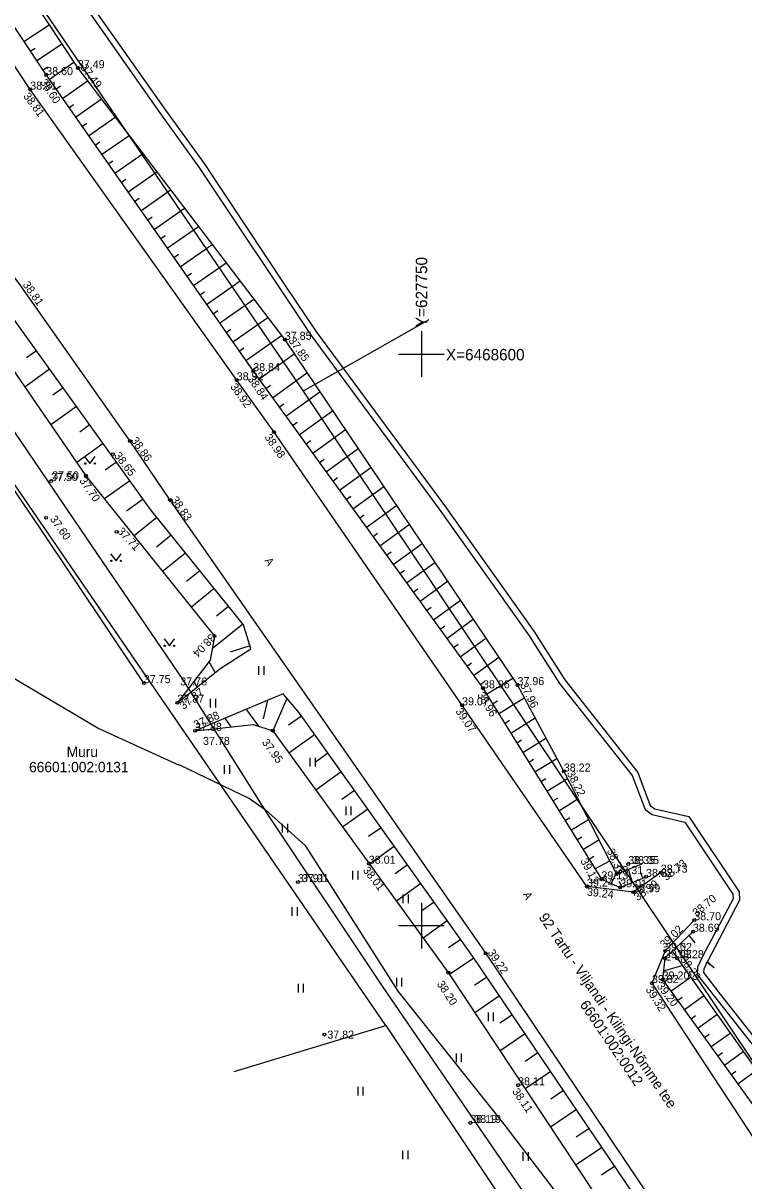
# Model space of a CAD drawing. Extents: x 627548 to 628052, y 6467984 to 6468802.
# Drawn here: x 627715.2 to 627778.2, y 6468527.7 to 6468629 of the extents above; entities that cross this region are included whole.
import ezdxf

# ---------------------------------------------------------------- set-up
doc = ezdxf.new("R2010")
doc.units = 0
for name, color, linetype in [('HALJASTUS', 7, 'Continuous'), ('KORGUS-EH2000', 7, 'Continuous'), ('KPKAABEL', 7, 'Continuous'), ('MOOTKORG-EH2000', 7, 'Continuous'), ('MOOTMPUNKT', 7, 'Continuous'), ('MPKAABEL', 7, 'Continuous'), ('PIIR', 7, 'Continuous'), ('RELJEEF', 7, 'Continuous'), ('SITRASS', 7, 'Continuous'), ('TEE', 7, 'Continuous'), ('VORK', 7, 'Continuous')]:
    doc.layers.add(name, color=color, linetype=linetype)

msp = doc.modelspace()

# ---------------------------------------------------------------- linework, layer by layer
at = {"layer": 'HALJASTUS'}
for p, q in [((627720.53, 6468591.03), (627720.99, 6468590.42)), ((627720.99, 6468590.42), (627721.44, 6468591.03)), ((627722.81, 6468582.51), (627723.28, 6468581.91)), ((627723.28, 6468581.91), (627723.72, 6468582.51)), ((627727.48, 6468575.09), (627727.95, 6468574.48)), ((627727.95, 6468574.48), (627728.39, 6468575.09)), ((627735.75, 6468572.71), (627735.75, 6468571.95)), ((627736.21, 6468572.71), (627736.21, 6468571.95)), ((627731.53, 6468569.84), (627731.53, 6468569.08)), ((627731.98, 6468569.84), (627731.98, 6468569.08)), ((627732.74, 6468564.03), (627732.74, 6468563.27)), ((627733.2, 6468564.03), (627733.2, 6468563.27)), ((627740.25, 6468564.67), (627740.25, 6468563.91)), ((627740.7, 6468564.67), (627740.7, 6468563.91)), ((627743.39, 6468560.42), (627743.39, 6468559.66)), ((627743.84, 6468560.42), (627743.84, 6468559.66)), ((627737.83, 6468558.9), (627737.83, 6468558.14)), ((627738.29, 6468558.9), (627738.29, 6468558.14)), ((627743.98, 6468554.8), (627743.98, 6468554.04)), ((627744.43, 6468554.8), (627744.43, 6468554.04)), ((627748.38, 6468552.72), (627748.38, 6468551.96)), ((627748.84, 6468552.72), (627748.84, 6468551.96)), ((627738.67, 6468551.61), (627738.67, 6468550.85)), ((627739.12, 6468551.61), (627739.12, 6468550.85)), ((627739.21, 6468544.9), (627739.21, 6468544.14)), ((627739.66, 6468544.9), (627739.66, 6468544.14)), ((627747.82, 6468545.44), (627747.82, 6468544.68)), ((627748.27, 6468545.44), (627748.27, 6468544.68)), ((627755.83, 6468542.39), (627755.83, 6468541.63)), ((627756.29, 6468542.39), (627756.29, 6468541.63)), ((627753.04, 6468538.8), (627753.04, 6468538.04)), ((627753.49, 6468538.8), (627753.49, 6468538.04)), ((627744.43, 6468535.89), (627744.43, 6468535.13)), ((627744.88, 6468535.89), (627744.88, 6468535.13)), ((627748.36, 6468530.31), (627748.36, 6468529.55)), ((627748.82, 6468530.31), (627748.82, 6468529.55)), ((627758.87, 6468530.18), (627758.87, 6468529.41)), ((627759.33, 6468530.18), (627759.33, 6468529.41))]:
    msp.add_line(p, q, dxfattribs=at)
msp.add_lwpolyline([(627725.71, 6468571.21), (627716.57, 6468584.87), (627692.41, 6468620.36), (627689.62, 6468619.76), (627687.7, 6468623.54), (627673.32, 6468620.74)], dxfattribs=at)
for centre in [(627720.59, 6468590.42), (627721.42, 6468590.42), (627722.87, 6468581.91), (627723.7, 6468581.91), (627727.54, 6468574.48), (627728.37, 6468574.48)]:
    msp.add_circle(centre, 0.055, dxfattribs=at)
at = {"layer": 'KORGUS-EH2000'}
for centre in [(627737.11, 6468593.18), (627724.5, 6468592.39), (627723.01, 6468591.24), (627720.65, 6468589.36), (627727.99, 6468587.24), (627717.17, 6468585.68), (627723.32, 6468584.45), (627731.9, 6468575.33), (627736.99, 6468567.06), (627755.63, 6468547.57), (627752.35, 6468545.88), (627741.51, 6468540.46)]:
    msp.add_circle(centre, 0.125, dxfattribs=at)
at = {"layer": 'KPKAABEL'}
msp.add_lwpolyline([(627720.22, 6468630.9), (627727.16, 6468621.02), (627730.53, 6468616.36), (627740.36, 6468601.62), (627751.57, 6468586.44), (627759.38, 6468575.45), (627762.1, 6468571.17), (627768.45, 6468563.13), (627769.58, 6468560.16), (627770.19, 6468559.71), (627773.06, 6468559.04), (627777.25, 6468552.76), (627777.27, 6468552.35), (627774.64, 6468547.34), (627774.16, 6468546.37), (627774.13, 6468545.73), (627783.66, 6468533.61)], dxfattribs=at)
at = {"layer": 'MOOTMPUNKT'}
for centre in [(627719.94, 6468625.01), (627717.17, 6468624.41), (627715.77, 6468623.14), (627738.05, 6468601.25), (627735.28, 6468598.51), (627733.84, 6468597.71), (627717.59, 6468588.89), (627725.71, 6468571.21), (627758.41, 6468571.04), (627755.39, 6468570.76), (627728.65, 6468569.5), (627753.56, 6468569.27), (627730.2, 6468567.04), (627762.46, 6468563.48), (627745.4, 6468555.41), (627768.1, 6468555.38), (627739.19, 6468553.8), (627765.75, 6468554.05), (627767.07, 6468554.5), (627769.66, 6468554.26), (627770.95, 6468554.63), (627764.49, 6468553.41), (627767.4, 6468553.34), (627768.55, 6468552.92), (627773.88, 6468550.47), (627773.76, 6468549.46), (627771.33, 6468547.78), (627771.3, 6468547.15), (627772.37, 6468547.14), (627770.18, 6468544.97), (627771.11, 6468545.29), (627758.46, 6468536.03), (627754.28, 6468532.73)]:
    msp.add_circle(centre, 0.125, dxfattribs=at)
at = {"layer": 'MPKAABEL'}
for points in [[(627709.2, 6468657.56), (627707.12, 6468655.82), (627706.53, 6468653.29), (627707.58, 6468652.36), (627708.93, 6468649.42), (627714.12, 6468640.74), (627720.67, 6468631.21), (627727.6, 6468621.34), (627730.99, 6468616.67), (627738.1, 6468605.93), (627740.81, 6468601.93), (627752.03, 6468586.76), (627759.83, 6468575.75), (627762.55, 6468571.49), (627768.93, 6468563.4), (627770.03, 6468560.51), (627770.43, 6468560.22), (627773.4, 6468559.54), (627777.8, 6468552.94), (627777.83, 6468552.22), (627775.03, 6468546.87), (627775.6, 6468546.31)], [(627775.61, 6468546.29), (627774.98, 6468546.79), (627774.72, 6468546.18), (627774.69, 6468545.9), (627776.11, 6468544.04), (627784.09, 6468533.94), (627791.95, 6468523.77), (627800.68, 6468512.58), (627810.04, 6468500.51), (627813.46, 6468495.35), (627814.99, 6468492.48), (627821.28, 6468482.3), (627827.85, 6468471.01), (627838.64, 6468452.75), (627843.99, 6468447.78), (627852.33, 6468430.34), (627859.23, 6468424.97)]]:
    msp.add_lwpolyline(points, dxfattribs=at)
at = {"layer": 'PIIR'}
for p, q in [((627666.22, 6468704.47), (627739.66, 6468596.76)), ((627746.88, 6468541.25), (627688.18, 6468626.77)), ((627750.64, 6468603), (627739.66, 6468596.76)), ((627739.66, 6468596.76), (627806.32, 6468497.36)), ((627733.62, 6468537.24), (627746.88, 6468541.25)), ((627746.88, 6468541.25), (627793.5, 6468471.53))]:
    msp.add_line(p, q, dxfattribs=at)
at = {"layer": 'RELJEEF'}
for p, q in [((627715.22, 6468627.34), (627717.43, 6468628.81)), ((627715.77, 6468626.51), (627716.19, 6468626.78)), ((627716.32, 6468625.67), (627718.53, 6468627.14)), ((627716.88, 6468624.84), (627717.29, 6468625.12)), ((627717.44, 6468624.01), (627719.6, 6468625.53)), ((627718.59, 6468622.37), (627720.78, 6468623.91)), ((627718.01, 6468623.19), (627718.42, 6468623.48)), ((627719.16, 6468621.55), (627719.57, 6468621.84)), ((627719.73, 6468620.74), (627722, 6468622.32)), ((627720.88, 6468619.1), (627723.21, 6468620.73)), ((627720.31, 6468619.92), (627720.71, 6468620.2)), ((627722.02, 6468617.46), (627724.42, 6468619.13)), ((627721.45, 6468618.28), (627721.86, 6468618.56)), ((627722.6, 6468616.64), (627723.01, 6468616.92)), ((627723.17, 6468615.82), (627725.64, 6468617.54)), ((627724.32, 6468614.18), (627726.85, 6468615.95)), ((627723.74, 6468615), (627724.15, 6468615.29)), ((627724.89, 6468613.36), (627725.3, 6468613.65)), ((627725.46, 6468612.54), (627728.06, 6468614.36)), ((627726.61, 6468610.9), (627729.28, 6468612.77)), ((627726.04, 6468611.72), (627726.45, 6468612.01)), ((627727.76, 6468609.26), (627730.49, 6468611.17)), ((627727.18, 6468610.08), (627727.59, 6468610.37)), ((627728.9, 6468607.62), (627731.7, 6468609.58)), ((627728.33, 6468608.44), (627728.74, 6468608.73)), ((627730.05, 6468605.99), (627732.91, 6468607.99)), ((627729.48, 6468606.81), (627729.89, 6468607.09)), ((627730.62, 6468605.17), (627731.03, 6468605.45)), ((627731.2, 6468604.35), (627734.13, 6468606.4)), ((627732.34, 6468602.71), (627735.34, 6468604.81)), ((627731.77, 6468603.53), (627732.18, 6468603.81)), ((627733.49, 6468601.07), (627736.55, 6468603.21)), ((627732.92, 6468601.89), (627733.33, 6468602.18)), ((627734.64, 6468599.43), (627737.77, 6468601.62)), ((627734.06, 6468600.25), (627734.47, 6468600.54)), ((627716.31, 6468600.29), (627715.45, 6468599.68)), ((627735.79, 6468597.8), (627738.87, 6468600.03)), ((627717.47, 6468598.67), (627715.3, 6468597.11)), ((627735.21, 6468598.61), (627735.62, 6468598.9)), ((627736.97, 6468596.18), (627739.99, 6468598.37)), ((627718.64, 6468597.05), (627717.76, 6468596.42)), ((627736.38, 6468596.99), (627736.79, 6468597.28)), ((627738.14, 6468594.56), (627741.11, 6468596.71)), ((627719.81, 6468595.42), (627717.57, 6468593.82)), ((627737.55, 6468595.37), (627737.96, 6468595.66)), ((627739.31, 6468592.94), (627742.23, 6468595.05)), ((627720.97, 6468593.8), (627720.12, 6468593.18)), ((627738.73, 6468593.75), (627739.13, 6468594.04)), ((627740.49, 6468591.32), (627743.35, 6468593.39)), ((627739.9, 6468592.13), (627740.31, 6468592.43)), ((627722.14, 6468592.17), (627719.85, 6468590.52)), ((627741.66, 6468589.7), (627744.46, 6468591.73)), ((627723.31, 6468590.55), (627722.32, 6468589.84)), ((627741.07, 6468590.51), (627741.48, 6468590.81)), ((627742.83, 6468588.08), (627745.58, 6468590.07)), ((627724.48, 6468588.92), (627722.27, 6468587.34)), ((627742.25, 6468588.89), (627742.65, 6468589.19)), ((627744.01, 6468586.46), (627746.7, 6468588.41)), ((627725.64, 6468587.3), (627724.19, 6468586.26)), ((627743.42, 6468587.27), (627743.83, 6468587.57)), ((627745.18, 6468584.84), (627747.82, 6468586.76)), ((627726.85, 6468585.71), (627724.86, 6468584.1)), ((627744.59, 6468585.65), (627745, 6468585.95)), ((627745.77, 6468584.03), (627746.17, 6468584.33)), ((627746.36, 6468583.22), (627748.94, 6468585.1)), ((627728.1, 6468584.15), (627726.82, 6468583.12)), ((627747.53, 6468581.6), (627750.06, 6468583.44)), ((627729.36, 6468582.59), (627727.36, 6468580.98)), ((627746.94, 6468582.41), (627747.35, 6468582.71)), ((627748.7, 6468579.99), (627751.17, 6468581.78)), ((627730.61, 6468581.03), (627729.45, 6468580.1)), ((627748.12, 6468580.8), (627748.52, 6468581.09)), ((627731.87, 6468579.48), (627729.87, 6468577.86)), ((627749.29, 6468579.18), (627749.69, 6468579.47)), ((627749.88, 6468578.37), (627752.29, 6468580.12)), ((627751.05, 6468576.75), (627753.41, 6468578.46)), ((627733.13, 6468577.92), (627732.08, 6468577.08)), ((627750.46, 6468577.56), (627750.87, 6468577.85)), ((627734.38, 6468576.36), (627731.7, 6468574.2)), ((627751.64, 6468575.94), (627752.04, 6468576.23)), ((627752.22, 6468575.13), (627754.53, 6468576.8)), ((627753.4, 6468573.51), (627755.65, 6468575.14)), ((627735, 6468574.47), (627733.27, 6468573.93)), ((627752.81, 6468574.32), (627753.21, 6468574.61)), ((627731.96, 6468572.14), (627731.41, 6468573.13)), ((627754.57, 6468571.89), (627756.77, 6468573.48)), ((627753.98, 6468572.7), (627754.39, 6468572.99)), ((627730.38, 6468570.88), (627730.1, 6468571.38)), ((627755.16, 6468571.08), (627755.56, 6468571.37)), ((627755.71, 6468570.24), (627757.99, 6468571.66)), ((627736.53, 6468569.71), (627736.16, 6468568.1)), ((627738.24, 6468569.87), (627736.99, 6468567.05)), ((627756.23, 6468569.39), (627756.66, 6468569.66)), ((627756.76, 6468568.54), (627759, 6468569.93)), ((627732.79, 6468568.14), (627733.34, 6468567.38)), ((627734.71, 6468568.89), (627735.76, 6468567.44)), ((627739.5, 6468568.33), (627738.37, 6468567.52)), ((627757.82, 6468566.84), (627759.95, 6468568.17)), ((627757.29, 6468567.69), (627757.71, 6468567.96)), ((627740.66, 6468566.7), (627738.41, 6468565.09)), ((627758.34, 6468565.99), (627758.77, 6468566.26)), ((627758.87, 6468565.15), (627760.89, 6468566.4)), ((627741.82, 6468565.07), (627740.7, 6468564.27)), ((627759.4, 6468564.3), (627759.82, 6468564.56)), ((627759.92, 6468563.45), (627761.84, 6468564.63)), ((627742.98, 6468563.44), (627740.76, 6468561.86)), ((627760.45, 6468562.6), (627760.88, 6468562.86)), ((627760.98, 6468561.75), (627762.78, 6468562.86)), ((627744.14, 6468561.81), (627743.04, 6468561.02)), ((627761.51, 6468560.9), (627761.93, 6468561.16)), ((627762.03, 6468560.05), (627763.69, 6468561.08)), ((627745.31, 6468560.18), (627743.11, 6468558.62)), ((627762.56, 6468559.2), (627762.98, 6468559.46)), ((627763.09, 6468558.35), (627764.61, 6468559.29)), ((627746.47, 6468558.56), (627745.38, 6468557.78)), ((627747.63, 6468556.93), (627745.46, 6468555.38)), ((627763.61, 6468557.5), (627764.04, 6468557.76)), ((627764.14, 6468556.65), (627765.53, 6468557.51)), ((627764.67, 6468555.8), (627765.09, 6468556.06)), ((627748.79, 6468555.3), (627747.71, 6468554.53)), ((627765.19, 6468554.95), (627766.48, 6468555.66)), ((627768.47, 6468553.78), (627768.11, 6468554.92)), ((627765.72, 6468554.1), (627766.15, 6468554.36)), ((627766.62, 6468553.68), (627767.05, 6468554.54)), ((627767.54, 6468553.4), (627767.35, 6468553.86)), ((627769.39, 6468554.15), (627769.2, 6468554.62)), ((627749.95, 6468553.67), (627747.81, 6468552.14)), ((627751.11, 6468552.04), (627750.05, 6468551.28)), ((627752.27, 6468550.41), (627750.16, 6468548.9)), ((627753.44, 6468548.79), (627752.38, 6468548.04)), ((627773.39, 6468549.12), (627773.92, 6468548.48)), ((627771.94, 6468547.75), (627772.43, 6468547.21)), ((627772.66, 6468548.44), (627773.01, 6468548.07)), ((627754.6, 6468547.16), (627752.46, 6468545.71)), ((627771.28, 6468547.03), (627771.78, 6468546.98)), ((627771.18, 6468546.03), (627772.81, 6468546.52)), ((627755.72, 6468545.5), (627754.64, 6468544.77)), ((627771.26, 6468545.09), (627771.66, 6468545.38)), ((627771.84, 6468544.27), (627773.54, 6468545.49)), ((627756.84, 6468543.84), (627754.67, 6468542.38)), ((627772.43, 6468543.46), (627772.83, 6468543.75)), ((627773.01, 6468542.65), (627774.69, 6468543.86)), ((627757.96, 6468542.19), (627756.87, 6468541.45)), ((627773.6, 6468541.84), (627774, 6468542.13)), ((627774.18, 6468541.03), (627775.85, 6468542.23)), ((627759.08, 6468540.53), (627756.88, 6468539.04)), ((627774.76, 6468540.22), (627775.17, 6468540.51)), ((627775.35, 6468539.41), (627777.01, 6468540.6)), ((627760.2, 6468538.88), (627759.09, 6468538.12)), ((627775.93, 6468538.59), (627776.34, 6468538.89)), ((627776.52, 6468537.78), (627778.16, 6468538.97)), ((627761.32, 6468537.22), (627759.08, 6468535.71)), ((627777.1, 6468536.97), (627777.51, 6468537.26)), ((627777.69, 6468536.16), (627779.32, 6468537.34)), ((627762.44, 6468535.56), (627761.32, 6468534.8)), ((627763.56, 6468533.91), (627761.29, 6468532.37)), ((627764.68, 6468532.25), (627763.54, 6468531.48)), ((627765.81, 6468530.59), (627763.5, 6468529.03)), ((627766.93, 6468528.94), (627765.77, 6468528.15))]:
    msp.add_line(p, q, dxfattribs=at)
for points in [[(627702.92, 6468655.93), (627699.82, 6468652.79), (627699.86, 6468650.45), (627717.17, 6468624.41), (627735.28, 6468598.51), (627755.39, 6468570.76), (627765.75, 6468554.05), (627767.4, 6468553.34), (627769.66, 6468554.26)], [(627703.6, 6468654.78), (627701.84, 6468652.32), (627719.94, 6468625.01), (627738.05, 6468601.25), (627758.41, 6468571.04), (627762.46, 6468563.48), (627767.07, 6468554.5), (627769.3, 6468555.39)], [(627728.65, 6468569.5), (627732.37, 6468572.47), (627735.08, 6468574.22), (627734.42, 6468576.31), (627726.29, 6468586.4), (627698.48, 6468625.1), (627696.02, 6468626.76), (627692.48, 6468627.58), (627682.04, 6468625.13)], [(627678.88, 6468623.38), (627689.28, 6468625.68), (627693.02, 6468626.09), (627696.85, 6468623.56), (627702.29, 6468615.53), (627710.84, 6468603.57), (627720.65, 6468589.36), (627731.9, 6468575.32), (627731.52, 6468573.22), (627728.65, 6468569.5)], [(627795.05, 6468466.68), (627801.81, 6468470.24), (627802.28, 6468472.49), (627801.25, 6468475.05), (627780.56, 6468508.79), (627754.57, 6468547.2), (627739.33, 6468568.57), (627737.9, 6468570.27), (627734.9, 6468569.03), (627730.2, 6468567.04)], [(627730.2, 6468567.04), (627735.3, 6468567.58), (627736.99, 6468567.05), (627752.35, 6468545.88), (627777.72, 6468507.56), (627798.51, 6468474.17), (627798.65, 6468472.14), (627793.54, 6468470.17)], [(627773.76, 6468549.46), (627771.3, 6468547.15), (627771.11, 6468545.29), (627781.2, 6468531.29), (627796.85, 6468507.37), (627811.93, 6468482.61), (627825.93, 6468458.24), (627843.64, 6468425.49), (627854.71, 6468402.3), (627862.1, 6468385.4), (627866.29, 6468377.39), (627871.18, 6468377.94)], [(627772.37, 6468547.14), (627782.44, 6468532.95), (627799.73, 6468507.29), (627814.06, 6468485.68), (627830.01, 6468459.01), (627845.39, 6468427.25), (627850.56, 6468416.94), (627856.09, 6468405.16), (627864.81, 6468385.75), (627868.21, 6468378.88), (627870.92, 6468379.12)]]:
    msp.add_lwpolyline(points, dxfattribs=at)
at = {"layer": 'SITRASS'}
for points in [[(627601.95, 6468775.67), (627611.52, 6468756.59), (627616.83, 6468745.3), (627619.18, 6468741.19), (627623.57, 6468733.68), (627630.72, 6468721.27), (627637.95, 6468708.68), (627647.64, 6468692.03), (627654.51, 6468680.48), (627661.91, 6468667.64), (627667.08, 6468659.84), (627674.13, 6468649.94), (627689.77, 6468629.54), (627695.63, 6468619.67), (627699.56, 6468614.68), (627710.37, 6468599.05), (627720.66, 6468583.91), (627729.18, 6468571.42), (627736.57, 6468559.7), (627746.58, 6468544.71), (627757.27, 6468529.07), (627768.1, 6468513.35)], [(627707.71, 6468575.88), (627708.41, 6468575.46), (627714.19, 6468571.72), (627721.76, 6468567.25), (627728.8, 6468564.04), (627728.83, 6468564.07), (627734.95, 6468561.12), (627736.34, 6468560.17), (627739.82, 6468557), (627747.95, 6468544.25), (627757.22, 6468532.63), (627766.08, 6468521.03)]]:
    msp.add_lwpolyline(points, dxfattribs=at)
at = {"layer": 'TEE'}
for points in [[(627770.95, 6468554.63), (627768.55, 6468552.92), (627764.49, 6468553.41), (627737.11, 6468593.18), (627733.84, 6468597.71), (627715.77, 6468623.14), (627708.91, 6468633.53), (627697.58, 6468649.47), (627698.48, 6468652.5), (627699.47, 6468653.84), (627702.73, 6468656.27)], [(627678.51, 6468625.34), (627686.44, 6468627.07), (627688.38, 6468627.55), (627694.21, 6468628.78), (627697.95, 6468628.29), (627705.76, 6468618.13), (627714.78, 6468606.18), (627724.5, 6468592.39), (627727.99, 6468587.23), (627755.63, 6468547.56), (627781.22, 6468509.46), (627802.36, 6468475.11), (627803.6, 6468472.53), (627802.84, 6468469.11), (627801.16, 6468467.82), (627794.97, 6468465.06)], [(627773.88, 6468550.47), (627771.33, 6468547.78), (627770.18, 6468544.97), (627779.72, 6468530.38), (627790.19, 6468514.89), (627795.6, 6468506.27), (627810.36, 6468482.16), (627820.25, 6468465.61), (627824.79, 6468457.18), (627842.02, 6468424.68), (627853.22, 6468402.01), (627861.19, 6468384.86), (627867.23, 6468371.17), (627873.07, 6468356.38), (627889.26, 6468318.91), (627892.45, 6468311.43), (627896.87, 6468301.52), (627899.4, 6468301.54), (627901.63, 6468302.36)]]:
    msp.add_lwpolyline(points, dxfattribs=at)
at = {"layer": 'VORK'}
for p, q in [((627750, 6468602), (627750, 6468598)), ((627748, 6468600), (627752, 6468600)), ((627750, 6468552), (627750, 6468548)), ((627748, 6468550), (627752, 6468550))]:
    msp.add_line(p, q, dxfattribs=at)

# ---------------------------------------------------------------- texts
at = {"layer": 'KORGUS-EH2000'}
for s, rotation, p in [('37.49', 307.5665, (627720.13, 6468625.05)), ('38.60', 303.4529, (627716.61, 6468623.79)), ('38.81', 306.8549, (627715.12, 6468622.56)), (' 38.81', 305.153, (627714.93, 6468606.28)), ('37.85', 305.4501, (627738.33, 6468601.18)), ('38.92', 305.7974, (627733.24, 6468597.14)), ('38.84', 304.6296, (627734.76, 6468597.82)), (' 38.86', 305.153, (627724.41, 6468592.66)), (' 38.98', 304.9471, (627736.09, 6468592.94)), (' 38.65', 307.6506, (627722.92, 6468591.31)), (' 37.70', 304.6141, (627719.89, 6468589.14)), (' 38.83', 304.8625, (627727.92, 6468587.47)), (' 37.60', 305.1726, (627717.31, 6468585.78)), (' 37.71', 313.2275, (627723.17, 6468584.64)), (' 38.04', 226.4687, (627731.73, 6468575.78)), ('37.96', 296.4558, (627758.62, 6468571.06)), ('37.87', 37.7132, (627729.18, 6468568.86)), ('38.96', 301.0788, (627754.86, 6468570.19)), ('39.07', 304.0311, (627752.95, 6468568.75)), ('37.88', 23.8982, (627730.26, 6468567.2)), (' 37.95', 305.9507, (627735.86, 6468566.23)), ('38.22', 296.944, (627762.71, 6468563.32)), ('39.13', 297.9393, (627763.89, 6468555.67)), ('38.31', 294.5261, (627766.21, 6468556.55)), ('38.01', 308.2407, (627744.84, 6468554.82)), ('38.73', 37.4561, (627771.43, 6468553.88)), ('38.99', 36.1076, (627768.92, 6468552.12)), ('39.24', 353.6463, (627764.46, 6468552.63)), ('38.70', 39.5762, (627774.08, 6468550.76)), ('39.02', 44.2949, (627771.28, 6468547.97)), (' 39.22', 303.8864, (627755.62, 6468547.85)), ('38.28', 304.4256, (627772.61, 6468547.06)), (' 38.20', 303.5086, (627751.18, 6468545.11)), ('39.32', 302.4859, (627769.6, 6468544.4)), ('39.20', 307.2944, (627770.56, 6468544.7)), ('38.11', 304.5215, (627757.92, 6468535.48))]:
    msp.add_text(s, height=0.7, rotation=rotation, dxfattribs=at).set_placement(p)
for s, p in [('37.50', (627717.69, 6468589.04)), ('38.35', (627768.45, 6468555.38)), ('37.91', (627739.54, 6468553.8)), (' 37.82', (627741.51, 6468540.11)), ('38.19', (627754.63, 6468532.73))]:
    msp.add_text(s, height=0.7, dxfattribs=at).set_placement(p)
at = {"layer": 'MOOTKORG-EH2000'}
for s, p in [('37.49', (627719.94, 6468625.01)), ('38.60', (627717.17, 6468624.41)), ('38.81', (627715.77, 6468623.14)), ('37.85', (627738.05, 6468601.25)), ('38.92', (627733.84, 6468597.71)), ('38.84', (627735.28, 6468598.51)), ('37.50', (627717.59, 6468588.89)), ('37.75', (627725.71, 6468571.21)), ('37.76', (627728.9, 6468571.01)), ('38.96', (627755.39, 6468570.76)), ('37.96', (627758.41, 6468571.04)), ('37.87', (627728.65, 6468569.5)), ('39.07', (627753.56, 6468569.27)), ('37.88', (627730.2, 6468567.04)), ('37.78', (627730.89, 6468565.81)), ('38.22', (627762.46, 6468563.48)), ('38.01', (627745.4, 6468555.41)), ('38.35', (627768.1, 6468555.38)), ('38.31', (627767.07, 6468554.5)), ('38.82', (627769.66, 6468554.26)), ('38.73', (627770.95, 6468554.63)), ('37.91', (627739.19, 6468553.8)), ('39.24', (627764.49, 6468553.41)), ('39.13', (627765.75, 6468554.05)), ('39.01', (627767.4, 6468553.34)), ('38.99', (627768.55, 6468552.92)), ('38.70', (627773.88, 6468550.47)), ('38.69', (627773.76, 6468549.46)), ('39.03', (627771.3, 6468547.15)), ('39.02', (627771.33, 6468547.78)), ('38.28', (627772.37, 6468547.14)), ('39.20', (627771.11, 6468545.29)), ('39.32', (627770.18, 6468544.97)), ('38.11', (627758.46, 6468536.03)), ('38.19', (627754.28, 6468532.73))]:
    msp.add_text(s, height=0.7, dxfattribs=at).set_placement(p)
at = {"layer": 'PIIR'}
for s, p in [('Muru', (627718.96, 6468564.75)), ('66601:002:0131', (627715.67, 6468563.42))]:
    msp.add_text(s, height=0.9, dxfattribs=at).set_placement(p)
for s, p in [('92 Tartu - Viljandi - Kilingi-Nõmme tee', (627760.23, 6468550.72)), ('66601:002:0012', (627763.82, 6468543.08))]:
    msp.add_text(s, height=0.9, rotation=304.2712, dxfattribs=at).set_placement(p)
at = {"layer": 'TEE'}
for rotation, p in [(302.2201, (627736.24, 6468581.93)), (296.7871, (627758.86, 6468552.74))]:
    msp.add_text('A', height=0.7, rotation=rotation, dxfattribs=at).set_placement(p)
at = {"layer": 'VORK'}
msp.add_text('Y=627750 ', height=1, rotation=90, dxfattribs=at).set_placement((627750.51, 6468602.36))
msp.add_text('X=6468600 ', height=1, dxfattribs=at).set_placement((627752.15, 6468599.45))

doc.saveas('drawing.dxf')
